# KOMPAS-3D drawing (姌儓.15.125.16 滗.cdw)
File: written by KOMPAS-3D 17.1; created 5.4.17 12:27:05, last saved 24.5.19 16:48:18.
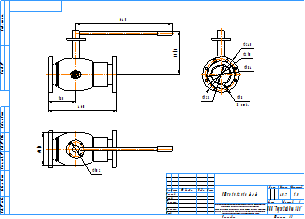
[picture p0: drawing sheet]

Sheet 1: A3, landscape

Title block, sheet 1: name: КШГИ.15.125.16 ф/ф; material: Сталь 20  ГОСТ 1050-2013; mass: 45,7; sheets: 1; organisation: ООО "Торговый дом АДЛ"; sheet format: A3; stored path: C:\Users\kka\KOMPAS_Work\КШП.ГИ\Ду100\КШГИ.15.100.16 ФФ ГЧ _ Кран шаровой газовый изолирующий БИВАЛ Ду100 Ру16 полнопроходной фланцевый Габаритный чертеж.cdw

Views: Вид 1, Проекционный вид 2, Проекционный вид 3
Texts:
  Klimkovich
  ADL
  Рама для чертежей
  Лит-Масса-Масштаб
  Материал-Предприятие
  Масштаб
  Изм.
  Лист
  № докум.
  Подп.
  Дата
  Лит.
  Разраб.
  Пров.
  Т.контр.
  Листов
  Внимание! Данный продукт является объектом авторского права ООО «Торговый Дом АДЛ».
  Запрещается изменение, копирование, распространение
  (в том числе путем копирования на другие сайты и ресурсы в Интернете)
  или любое иное использование информации и объектов без предварительного
  согласия правообладателя (ООО «Торговый Дом АДЛ»).
  Н.контр.
  Утв.
  Изменение
  Номер документа
  Подпись
  Обозначение документа
  Наименование изделия
  Масса изделия по ГОСТ 2.109-73
  Порядковый номер листа
  Общее количество листов в документе
  Характер работы, выполненной лицом, подписавшим документ
  Наименование или индекс предприятия, выпускающего документ
  Инв. № подл.
  Подп. и дата
  Взам. инв. №
  Инв. № дубл.
  Инвентарный номер подлинника по ГОСТ 2.501-68
  Подпись принявшего подлинник в отдел технической документации
  Инвентарный номер подлинника, взамен которого выпущен данный подлинник
  Инвентарный номер дубликата по ГОСТ 2.502-68
  Подпись принявшего дубликат в отдел технической документации
  Справ. №
  Перв. примен.
  Обозначение документа, взамен или на основании которого выпущен данный документ
  Обозначение документа, в котором впервые записан данный документ
  Подпись лица, копировавшего чертеж
  Обозначение формата листа
  !Рама для чертежа
Dimensions and other numbers on the sheet: 185; 460; 645; 291,6; 245; 210; 184; 123; 18; 8 отв.; 219; 102; 1:5; 1; 45,7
